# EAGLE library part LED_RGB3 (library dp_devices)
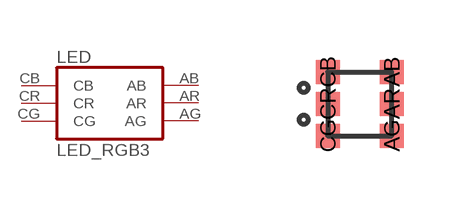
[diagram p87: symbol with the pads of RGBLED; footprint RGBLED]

Designator prefix LED

## LED_RGB3  [RGBLED]
AB  AB
AG  AG
AR  AR
CB  CB
CG  CG
CR  CR

## Footprint RGBLED (pad centres in mm)
smd 0.6 x 0.6: AB 0.8,0.8; AG 0.8,-0.8; AR 0.8,0; CB -0.8,0.8; CG -0.8,-0.8; CR -0.8,0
